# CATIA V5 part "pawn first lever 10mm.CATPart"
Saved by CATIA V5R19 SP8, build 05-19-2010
Part number: pawn first lever 10mm
Bounding box of the stored display mesh (mm): x 71.302 to 86.302, y 64.1 to 107.1, z 170.741 to 185.365
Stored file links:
  G:\EU_thinkMotion\CFAO_2010\MMS_groupe1\MMS_groupe1\A reprendre\gduval\CFAO kinematic ok\pawn first lever 10mm.CATPart
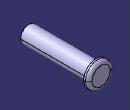
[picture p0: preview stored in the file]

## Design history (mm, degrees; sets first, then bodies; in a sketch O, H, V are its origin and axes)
Body1 (main body)
  Plane1: stored without definition
  Point1: stored without definition
  Sketch1 on Plane1, origin (0, 104.1, 0), H (-1, 0, 0), V (0, 0, 1)
    circle A1 centre (-78.802, 178.053) radius 5
    point P1 (-78.802, 178.053)
    reference projected point E1 (-78.802, 178.053) from Point1
    radius A1 = 5
    coincidence: P1 E1
  Pad1: profile Sketch1, direction (0, -1, 0), length 40
  Sketch2 on start face of Pad1, origin (0, 104.1, 0), H (-1, 0, 0), V (0, 0, 1)
    circle A1 centre (-78.802, 178.053) radius 7.5
    reference projected circle E2 centre (-78.802, 178.053) radius 5 from Sketch1.A1
    radius A1 = 7.5
    concentricity: A1 E2
  Pad2: profile Sketch2, direction (0, 1, 0), length 3
  Fillet1: radius 2, on end face of Pad2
